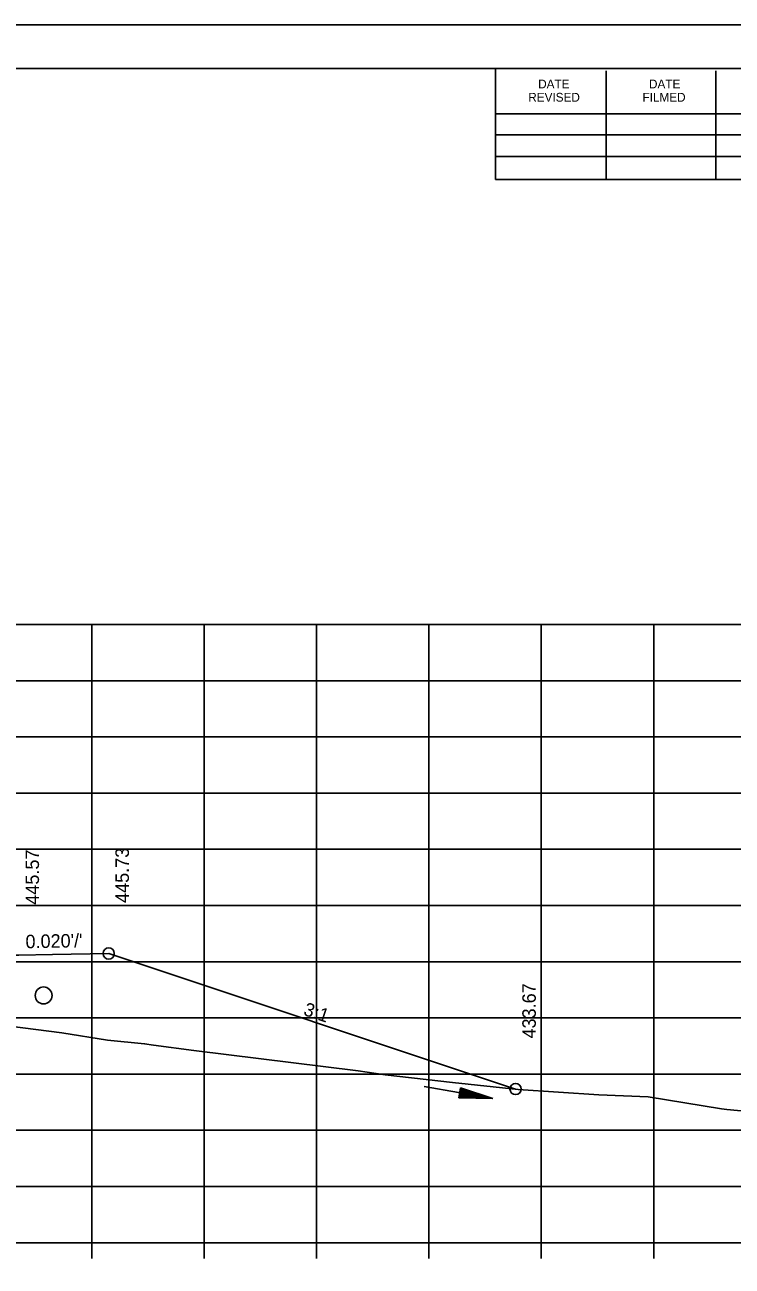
# Model space of a CAD drawing. Extents: x 1538688 to 1540766, y 656250 to 671912.
# Drawn here: x 1538892.2 to 1538955.2, y 668174.4 to 668284.8 of the extents above; entities that cross this region are included whole.
import ezdxf

# ---------------------------------------------------------------- set-up
doc = ezdxf.new("R2010")
doc.units = 0
for name, color, linetype in [('15', 7, 'Continuous'), ('18', 7, 'Continuous'), ('20', 7, 'Continuous'), ('22', 7, 'Continuous'), ('26', 7, 'Continuous'), ('39', 7, 'Continuous'), ('41', 7, 'Continuous'), ('42', 7, 'Continuous'), ('Borings', 7, 'Continuous'), ('RipRap', 7, 'Continuous')]:
    doc.layers.add(name, color=color, linetype=linetype)

msp = doc.modelspace()

# ---------------------------------------------------------------- linework, layer by layer
at = {"layer": '15'}
for p, q in [((1538930.83, 668189.37), (1538930.99, 668190.26)), ((1538930.92, 668189.88), (1538931.38, 668189.73)), ((1538930.94, 668189.96), (1538931.87, 668189.64)), ((1538930.95, 668190.03), (1538932.37, 668189.56)), ((1538930.96, 668190.11), (1538932.86, 668189.47)), ((1538930.97, 668190.18), (1538933.37, 668189.38)), ((1538930.99, 668190.26), (1538933.86, 668189.29)), ((1538930.83, 668189.37), (1538933.86, 668189.29)), ((1538930.84, 668189.45), (1538933.37, 668189.38)), ((1538930.86, 668189.52), (1538932.86, 668189.47)), ((1538930.87, 668189.59), (1538932.37, 668189.56)), ((1538930.88, 668189.67), (1538931.87, 668189.64)), ((1538930.9, 668189.75), (1538931.38, 668189.73))]:
    msp.add_line(p, q, dxfattribs=at)
at = {"layer": '18'}
msp.add_lwpolyline([(1538889.71, 668195.88), (1538895.52, 668195.13), (1538899.58, 668194.49), (1538902.88, 668194.17), (1538903.68, 668194.03), (1538907.25, 668193.57), (1538921.89, 668191.76), (1538924.3, 668191.4), (1538930.28, 668190.71), (1538936.12, 668190.11), (1538943.29, 668189.63), (1538947.7, 668189.44), (1538954.22, 668188.38), (1538954.69, 668188.32), (1538955.63, 668188.24), (1538961.22, 668187.77), (1538968.7, 668187.05), (1538984.98, 668185.74), (1538985.12, 668185.72), (1538985.18, 668185.72), (1538997.11, 668184.94), (1538998.18, 668184.87)], dxfattribs=at)
at = {"layer": '20'}
msp.add_lwpolyline([(1538806.76, 668205.51), (1538816.67, 668202.2), (1538821.67, 668202.1), (1538824.67, 668202.04), (1538825.17, 668202.04), (1538825.18, 668201.54), (1538826.18, 668201.56), (1538858.18, 668202.2), (1538890.18, 668201.56), (1538891.18, 668201.54), (1538891.19, 668202.04), (1538891.69, 668202.04), (1538894.69, 668202.1), (1538899.69, 668202.2), (1538935.89, 668190.14)], dxfattribs=at)
at = {"layer": '22'}
for p, q in [((1538718.18, 668231.47), (1538998.18, 668231.47)), ((1538718.18, 668231.47), (1538998.18, 668231.47)), ((1538898.18, 668176.47), (1538898.18, 668231.47)), ((1538898.18, 668176.47), (1538898.18, 668231.47)), ((1538908.18, 668176.47), (1538908.18, 668231.47)), ((1538908.18, 668176.47), (1538908.18, 668231.47)), ((1538918.18, 668176.47), (1538918.18, 668231.47)), ((1538918.18, 668176.47), (1538918.18, 668231.47)), ((1538928.18, 668176.47), (1538928.18, 668231.47)), ((1538928.18, 668176.47), (1538928.18, 668231.47)), ((1538938.18, 668176.47), (1538938.18, 668231.47)), ((1538938.18, 668176.47), (1538938.18, 668231.47)), ((1538948.18, 668176.47), (1538948.18, 668231.47)), ((1538948.18, 668176.47), (1538948.18, 668231.47)), ((1538718.18, 668226.47), (1538998.18, 668226.47)), ((1538718.18, 668226.47), (1538998.18, 668226.47)), ((1538718.18, 668221.47), (1538998.18, 668221.47)), ((1538718.18, 668221.47), (1538998.18, 668221.47)), ((1538718.18, 668216.47), (1538998.18, 668216.47)), ((1538718.18, 668216.47), (1538998.18, 668216.47)), ((1538718.18, 668211.47), (1538998.18, 668211.47)), ((1538718.18, 668211.47), (1538998.18, 668211.47)), ((1538718.18, 668206.47), (1538998.18, 668206.47)), ((1538718.18, 668206.47), (1538998.18, 668206.47)), ((1538718.18, 668201.47), (1538998.18, 668201.47)), ((1538718.18, 668201.47), (1538998.18, 668201.47)), ((1538718.18, 668196.47), (1538998.18, 668196.47)), ((1538718.18, 668196.47), (1538998.18, 668196.47)), ((1538718.18, 668191.47), (1538998.18, 668191.47)), ((1538718.18, 668191.47), (1538998.18, 668191.47)), ((1538718.18, 668186.47), (1538998.18, 668186.47)), ((1538718.18, 668186.47), (1538998.18, 668186.47)), ((1538718.18, 668181.47), (1538998.18, 668181.47)), ((1538718.18, 668181.47), (1538998.18, 668181.47)), ((1538718.18, 668176.47), (1538998.18, 668176.47)), ((1538718.18, 668176.47), (1538998.18, 668176.47))]:
    msp.add_line(p, q, dxfattribs=at)
at = {"layer": '26'}
msp.add_line((1538687.78, 668284.82), (1539021.11, 668284.82), dxfattribs=at)
msp.add_lwpolyline([(1538687.77, 668284.82), (1539021.11, 668284.82), (1539021.11, 668071.49), (1538687.77, 668071.49)], close=True, dxfattribs=at)
for centre in [(1538899.69, 668202.2), (1538935.89, 668190.14)]:
    msp.add_circle(centre, 0.5, dxfattribs=at)
at = {"layer": '39'}
msp.add_line((1538927.77, 668190.37), (1538933.86, 668189.29), dxfattribs=at)
msp.add_circle((1538893.9, 668198.47), 0.75, dxfattribs=at)
at = {"layer": 'Borings'}
for p, q in [((1538718.18, 668176.47), (1538998.18, 668176.47)), ((1538898.18, 668175.07), (1538898.18, 668176.47)), ((1538908.18, 668175.07), (1538908.18, 668176.47)), ((1538918.18, 668175.07), (1538918.18, 668176.47)), ((1538928.18, 668175.07), (1538928.18, 668176.47)), ((1538938.18, 668175.07), (1538938.18, 668176.47)), ((1538948.18, 668175.07), (1538948.18, 668176.47))]:
    msp.add_line(p, q, dxfattribs=at)
at = {"layer": 'RipRap'}
for p, q in [((1538700.18, 668280.93), (1539016.36, 668280.93)), ((1538934.1, 668271.05), (1538934.1, 668280.93)), ((1538943.96, 668271.05), (1538943.96, 668280.73)), ((1538953.72, 668271.05), (1538953.72, 668280.73)), ((1538934.1, 668276.91), (1538973.26, 668276.91)), ((1538934.1, 668275.05), (1538973.26, 668275.05)), ((1538934.1, 668271.05), (1538934.1, 668273.11)), ((1538934.1, 668273.11), (1538973.26, 668273.11)), ((1539016.36, 668271.05), (1538934.1, 668271.05))]:
    msp.add_line(p, q, dxfattribs=at)

# ---------------------------------------------------------------- texts
at = {"layer": '41'}
for s, p in [('445.57', (1538893.49, 668206.54)), ('445.73', (1538901.49, 668206.7)), ('433.67', (1538937.69, 668194.64))]:
    msp.add_text(s, height=1.2, rotation=90, dxfattribs=at).set_placement(p)
at = {"layer": '42'}
for s, rotation, p in [("0.020'/'", 1.1458, (1538892.3, 668202.66)), ('3:1', 341.5651, (1538916.94, 668196.75))]:
    msp.add_text(s, height=1.2, rotation=rotation, dxfattribs=at).set_placement(p)
at = {"layer": 'RipRap'}
for s, p in [('DATE', (1538937.9, 668279.17)), ('DATE', (1538947.76, 668279.17)), ('REVISED', (1538937.02, 668277.99)), ('FILMED', (1538947.18, 668277.99))]:
    msp.add_text(s, height=0.782, rotation=360, dxfattribs=at).set_placement(p)

doc.saveas('drawing.dxf')
